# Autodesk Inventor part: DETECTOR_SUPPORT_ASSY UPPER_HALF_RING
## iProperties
Shininess: 64.0
Length Units: 11272
Angle Units: 11279
Time Units: 11290
Mass Units: 11286
Length Display Precision: 3
Angle Display Precision: 2
Compacted: True
Part Number: DETECTOR_SUPPORT_ASSY UPPER_HALF_RING
Document SubType Name: Modeling
Created: 2004-08
Designer: John Blackburn
Material: ALUMINUM
Manufacturer: Standard
Standards Organization: Custom
Density: 0.0
Volumn: 0.0
Area: 0.0
PropertySet Name: Model Information
Control State: 0
Master: False
Checked Out: False
Author: John Blackburn
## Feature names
1. ExtrusionBlind1
2. AM_HOLE_SI0029_1 [Hole]
3. AM_HOLE_SI0029_2 [Hole]
4. Polar Pattern1 [Circular Pattern]
5. ExtrusionThru1
6. Hole1
7. Rectangular Pattern1
8. Hole2
9. Rectangular Pattern2
10. Hole5
11. Hole6
